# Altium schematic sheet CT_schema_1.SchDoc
size 729 x 589 mm
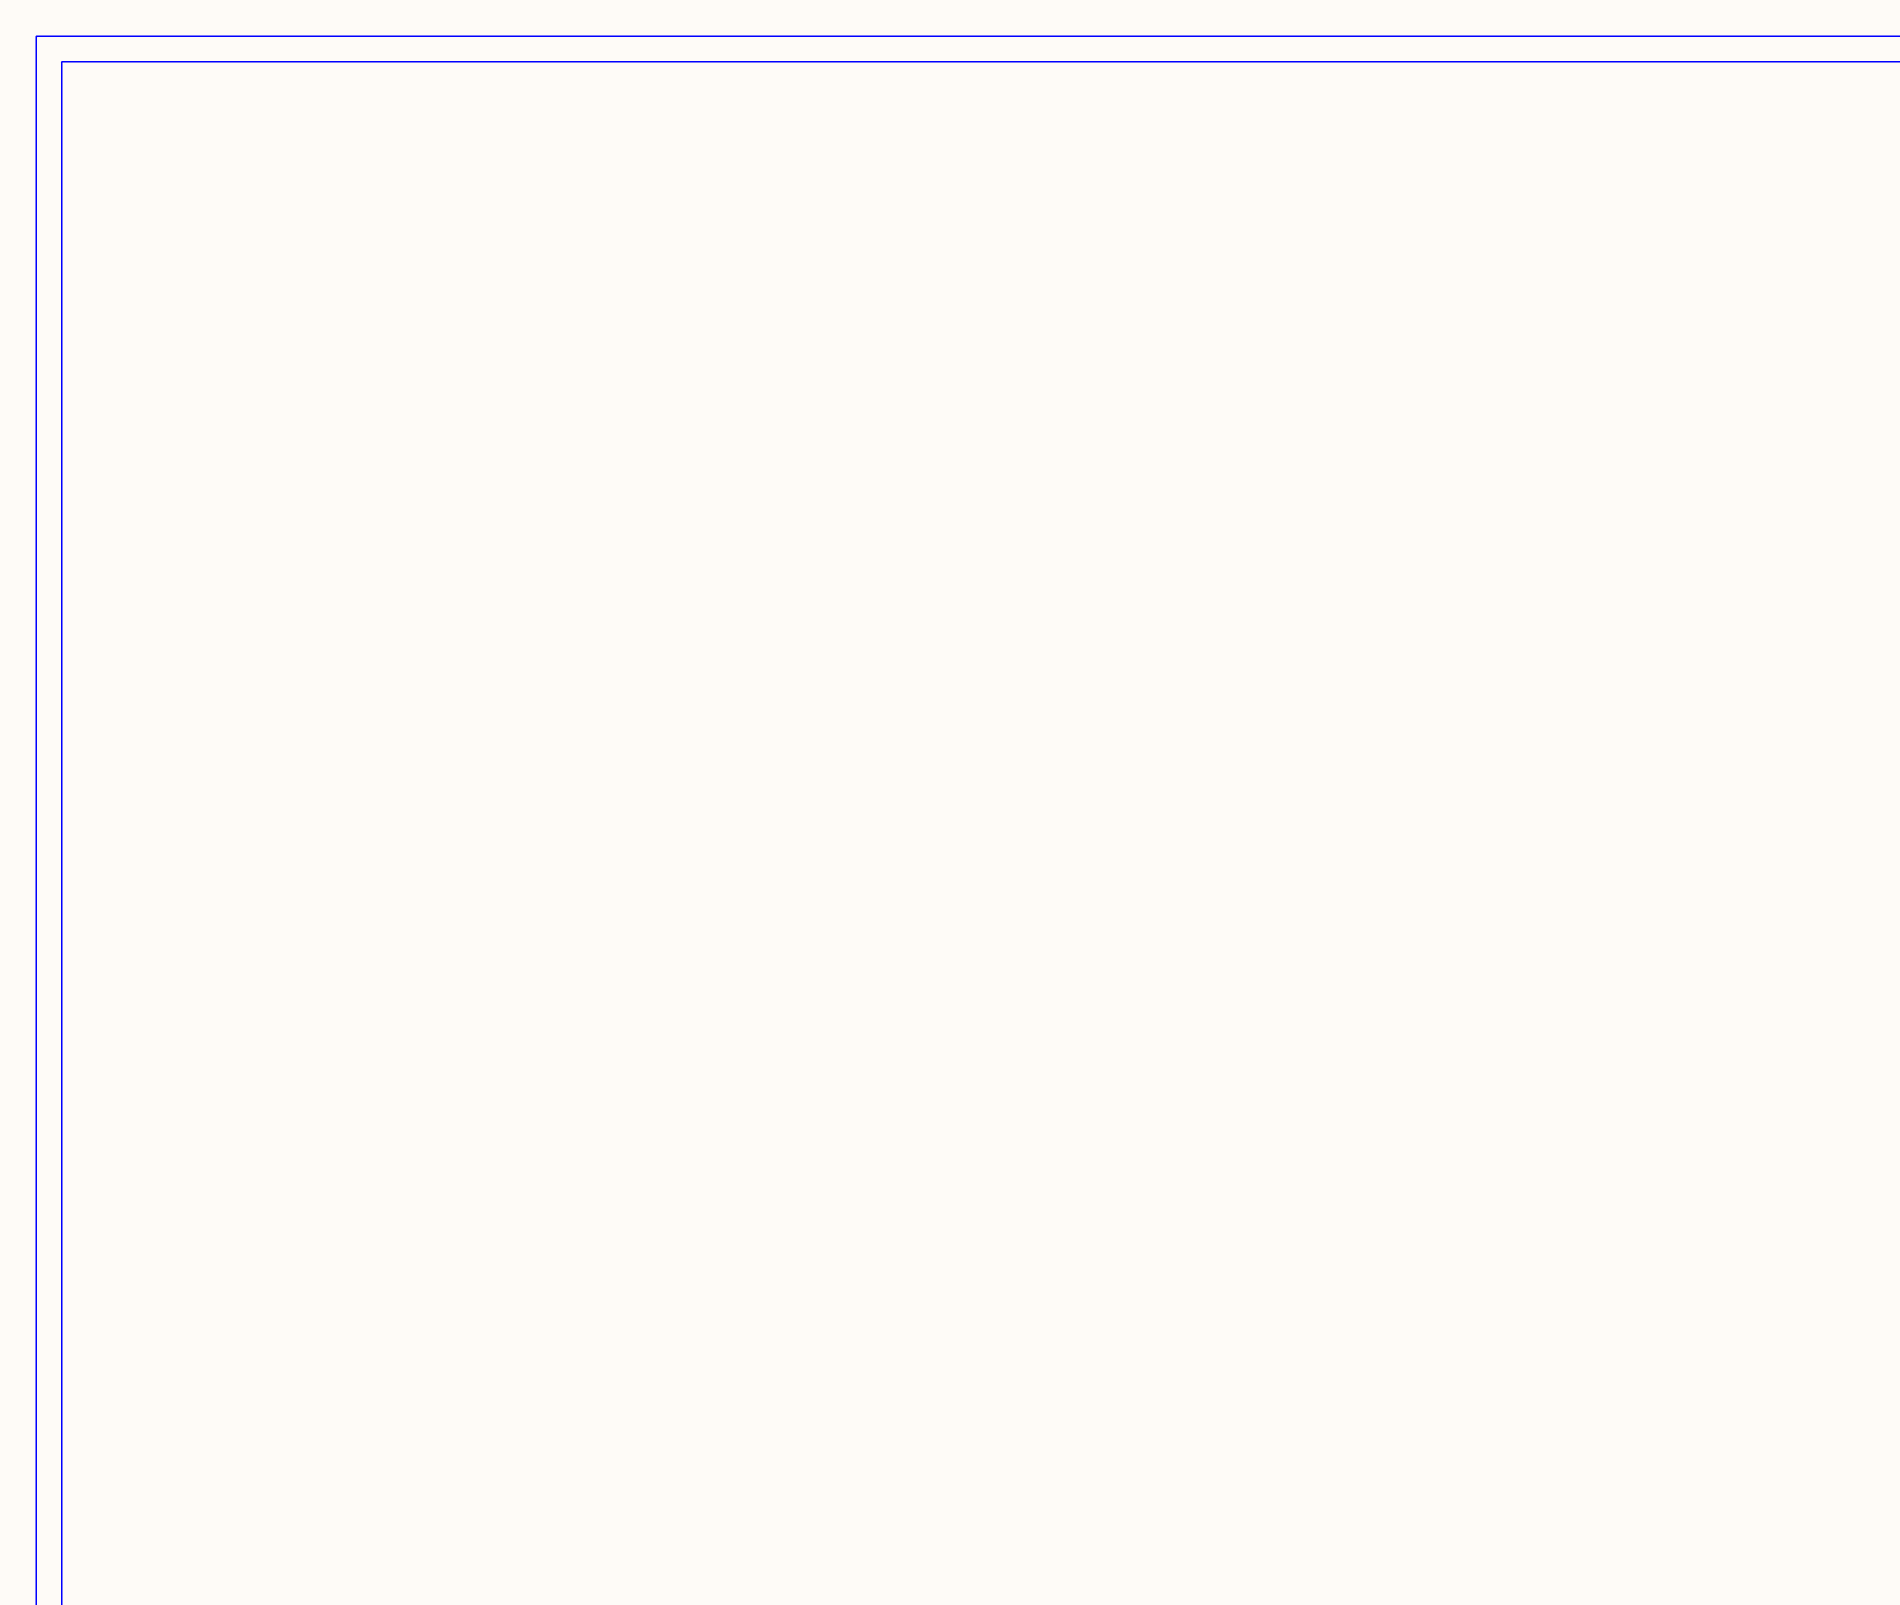
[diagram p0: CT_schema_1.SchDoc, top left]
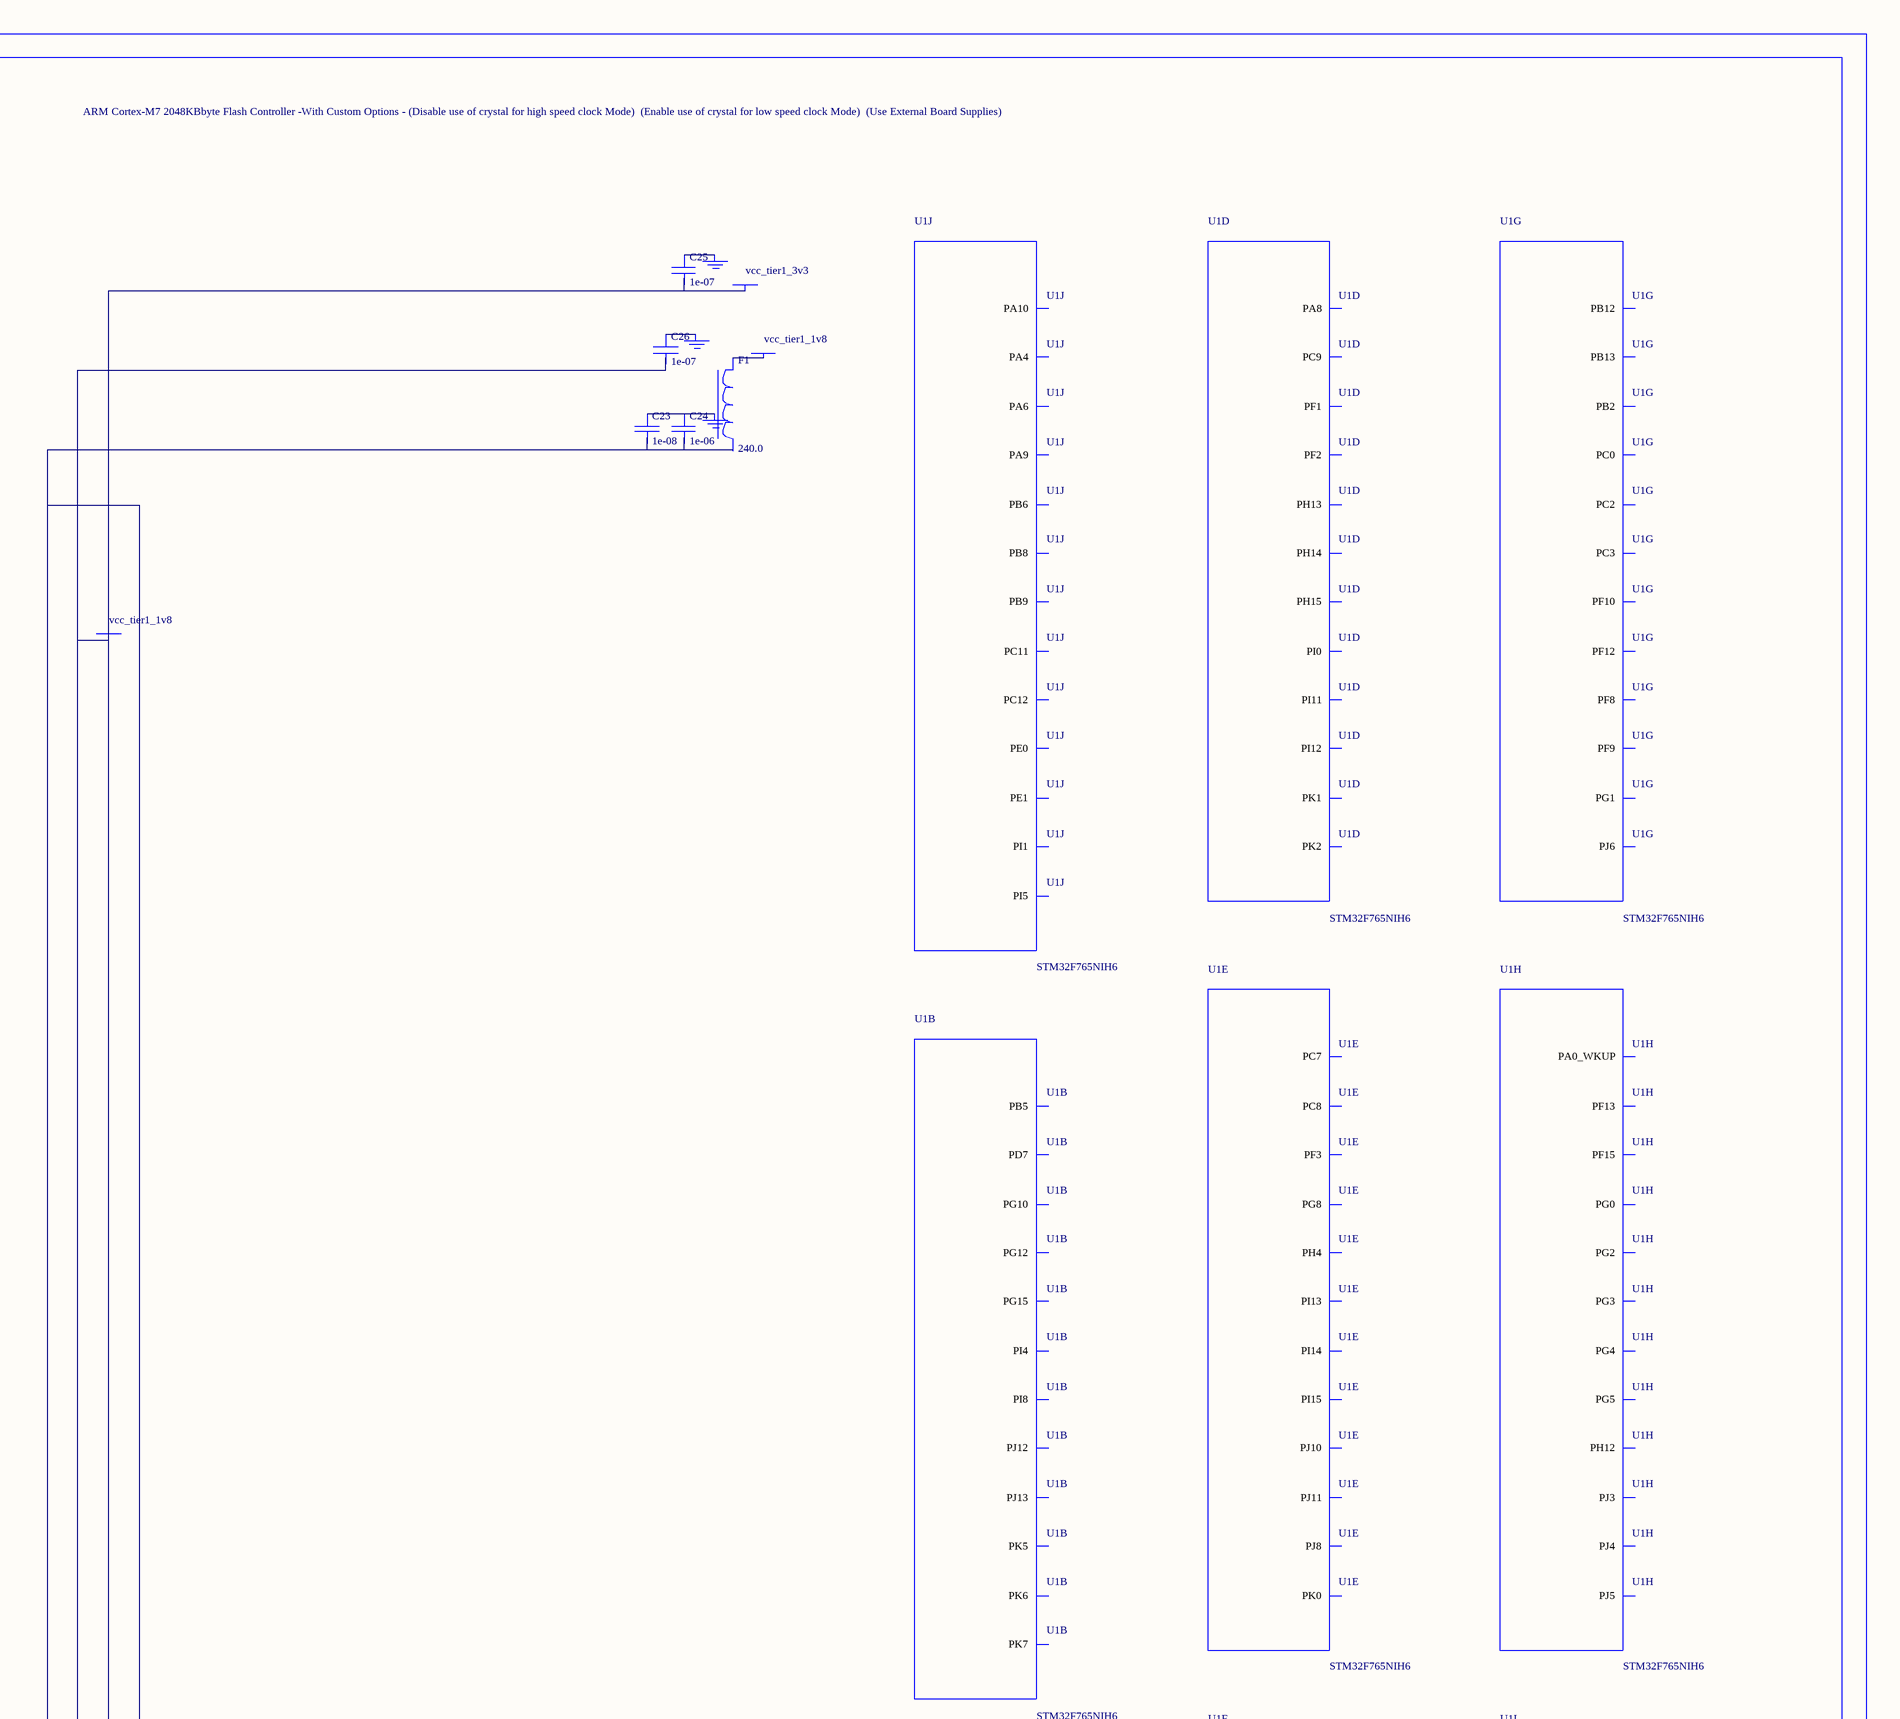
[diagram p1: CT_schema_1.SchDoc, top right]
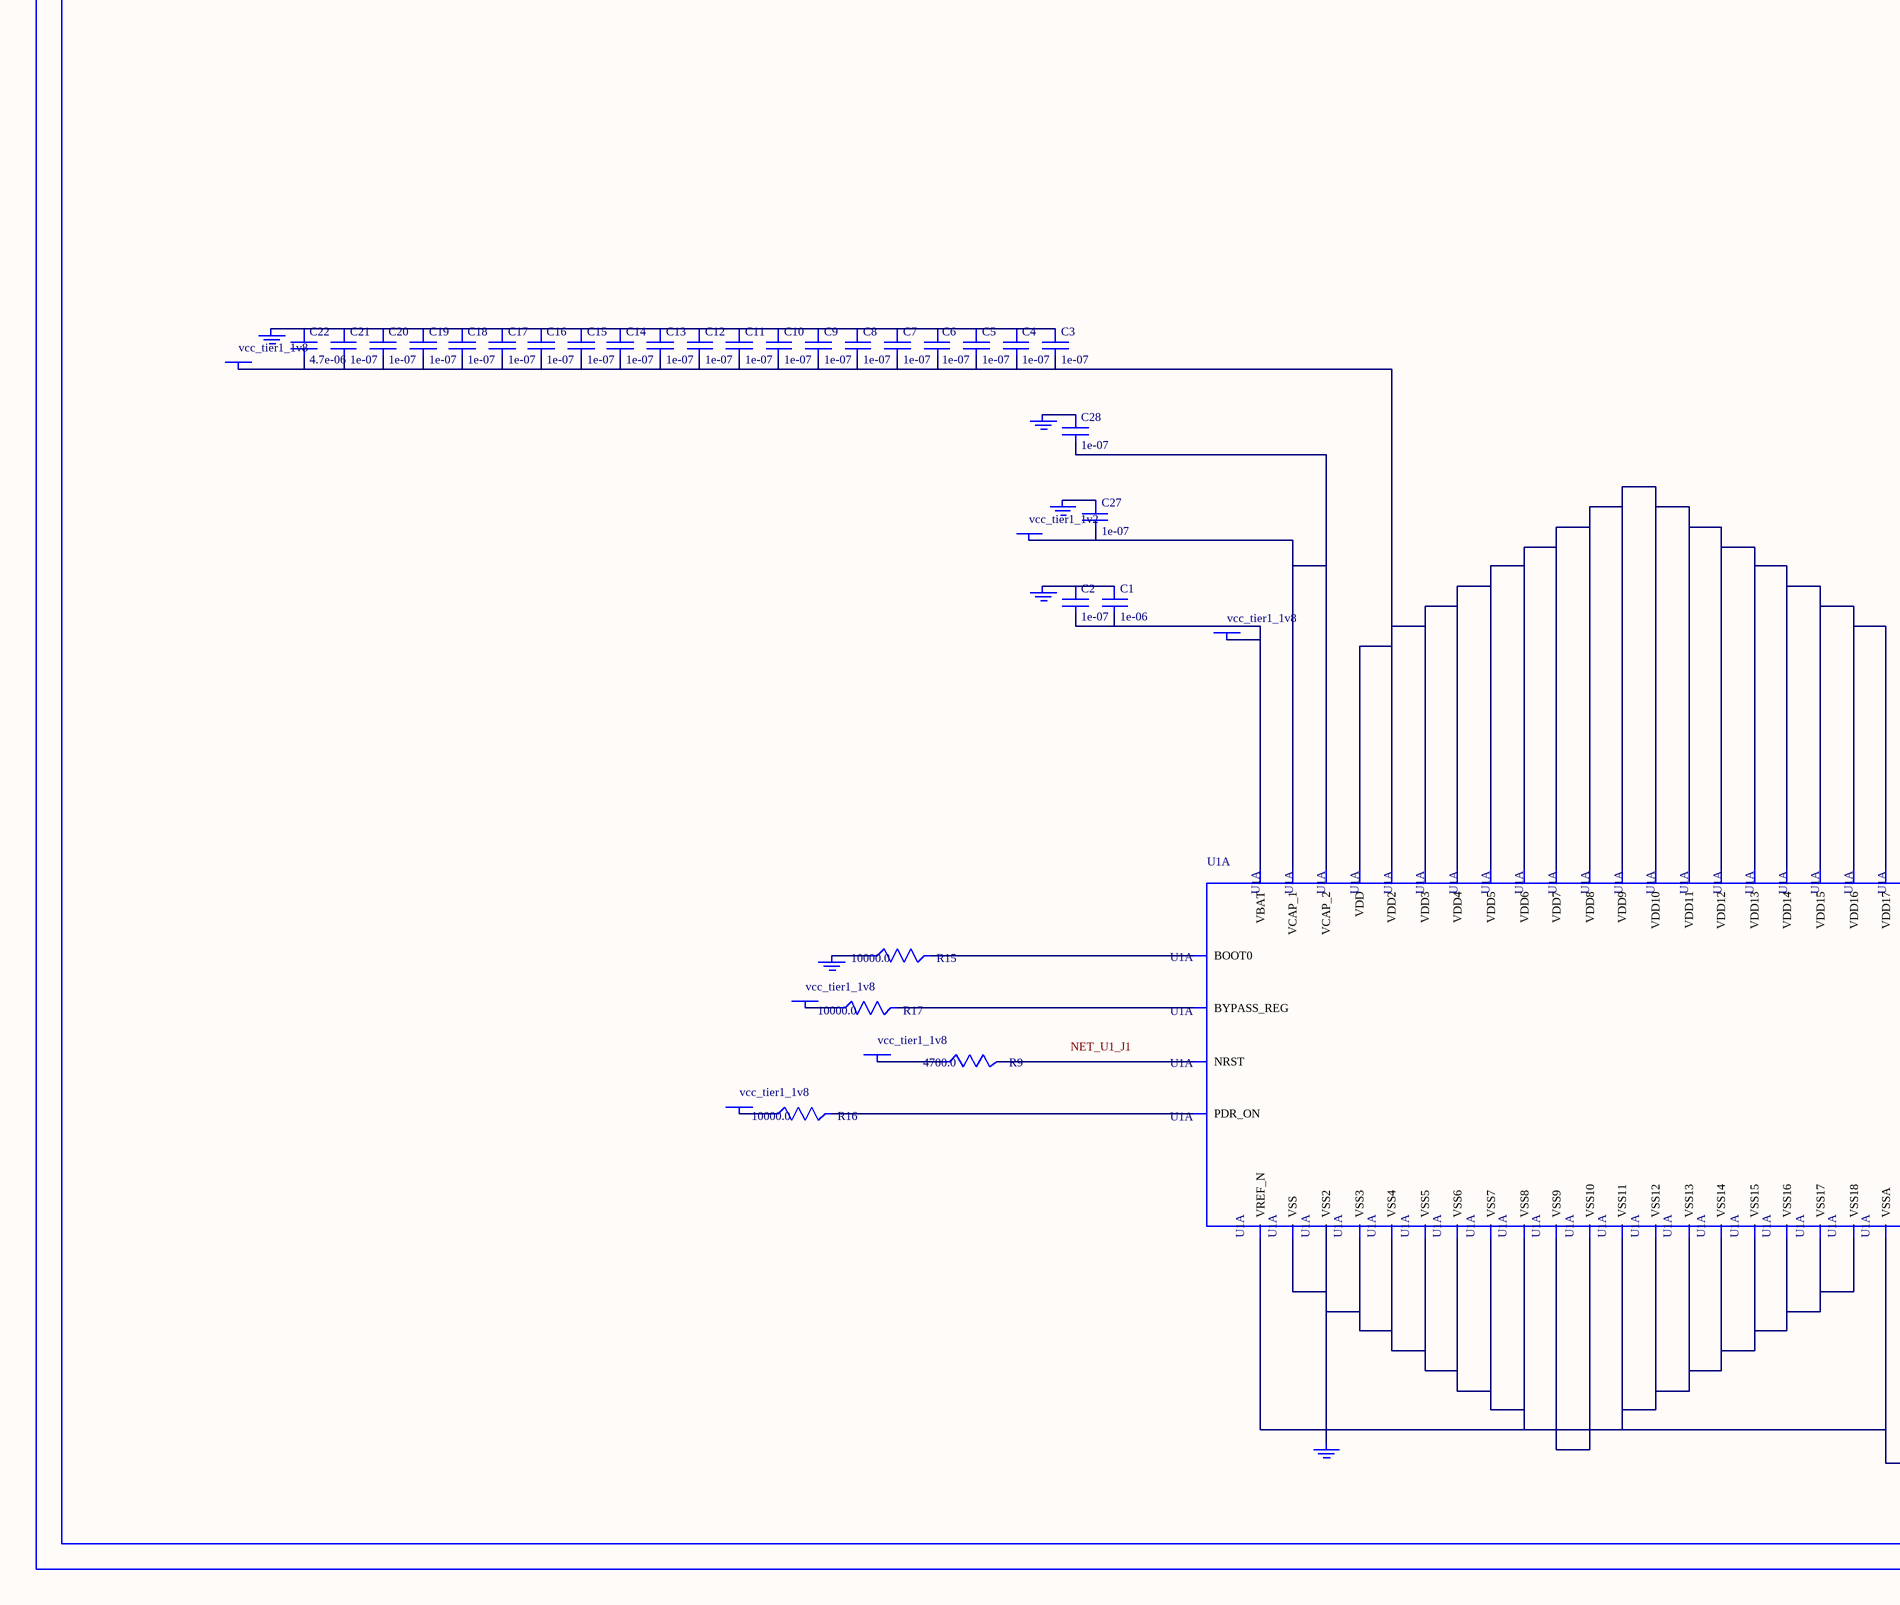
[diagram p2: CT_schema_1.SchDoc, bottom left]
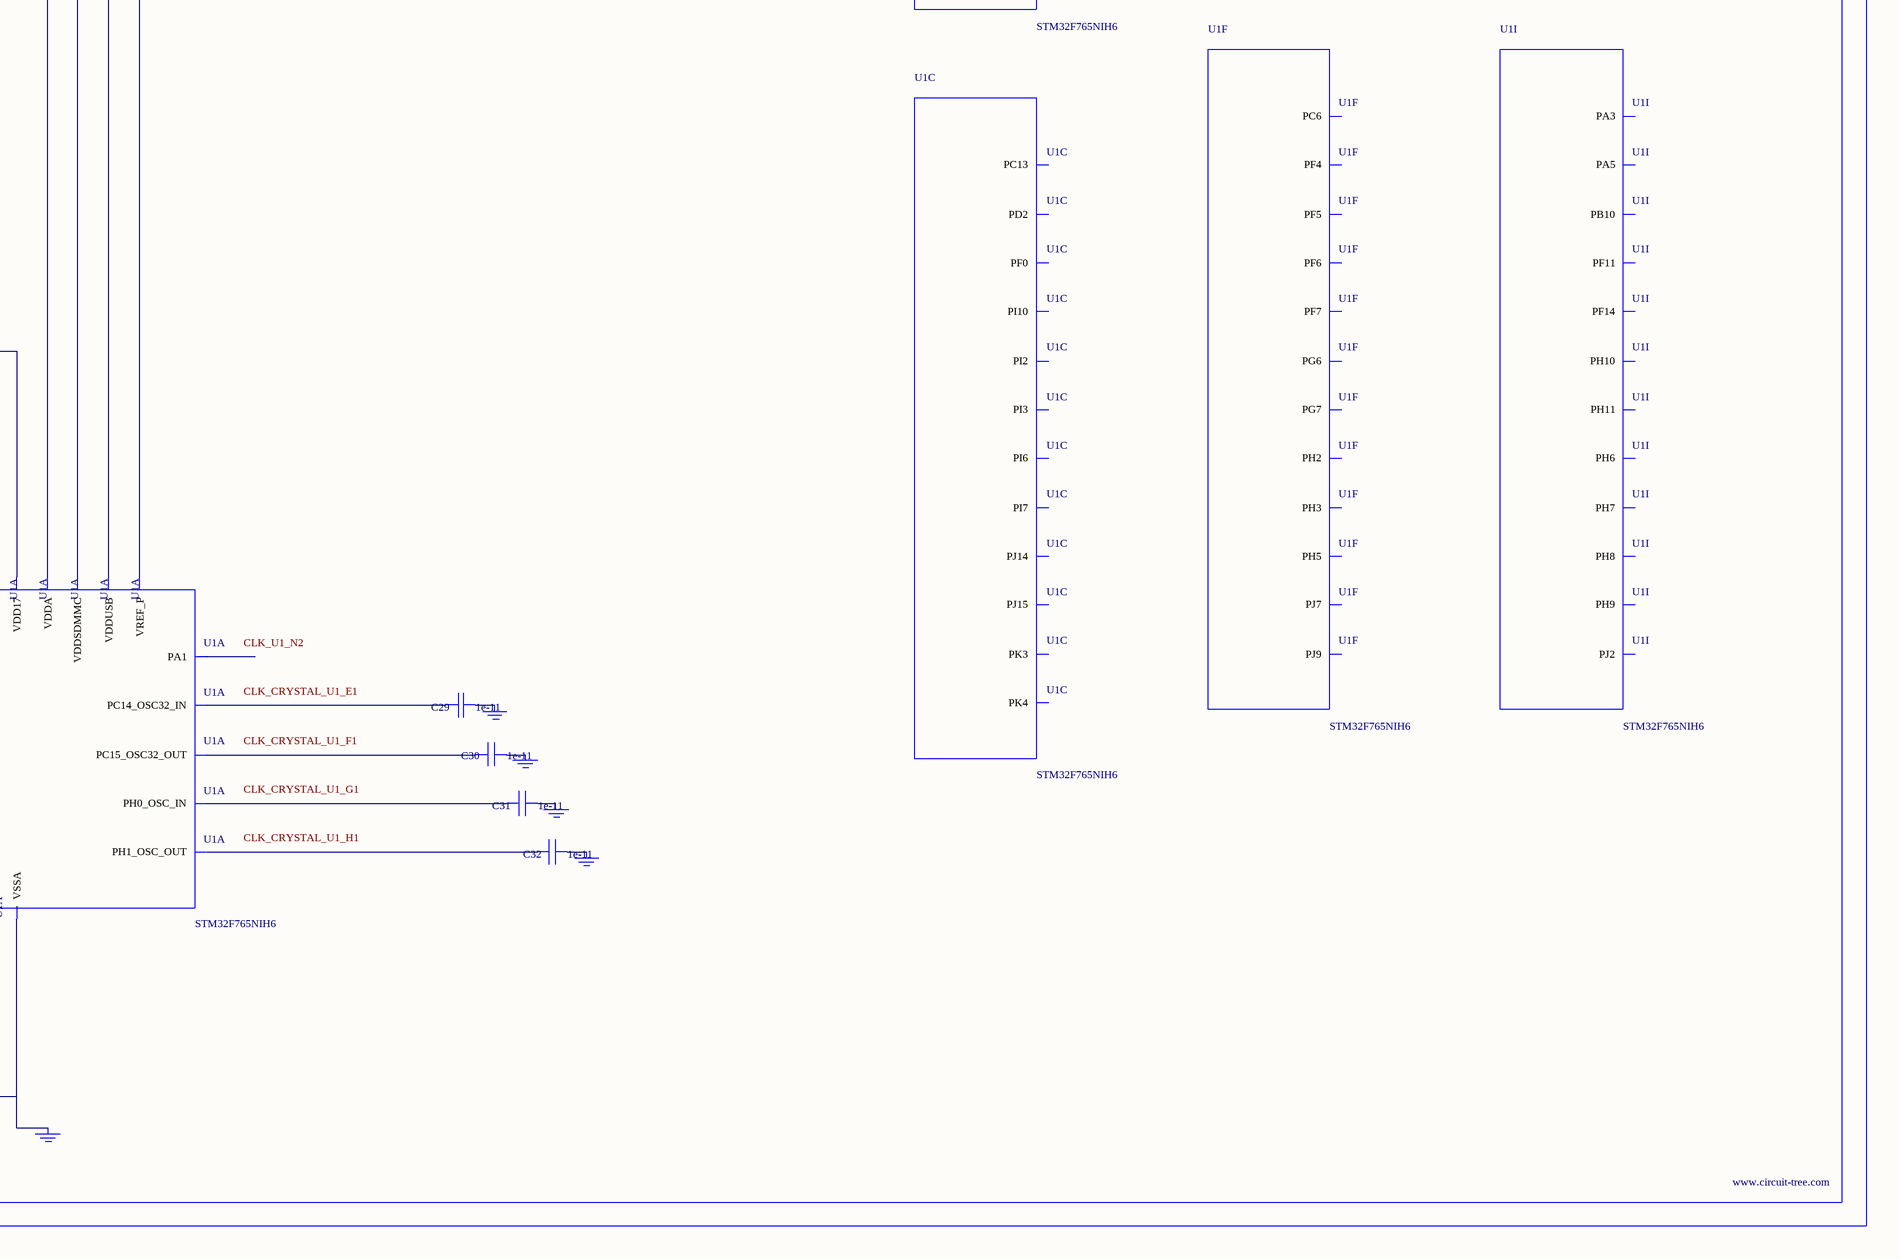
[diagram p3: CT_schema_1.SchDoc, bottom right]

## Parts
BORDER0  (no value)
C1  1e-06  [C0603]
C2  1e-07  [C0603]
C3  1e-07  [C0603]
C4  1e-07  [C0603]
C5  1e-07  [C0603]
C6  1e-07  [C0603]
C7  1e-07  [C0603]
C8  1e-07  [C0603]
C9  1e-07  [C0603]
C10  1e-07  [C0603]
C11  1e-07  [C0603]
C12  1e-07  [C0603]
C13  1e-07  [C0603]
C14  1e-07  [C0603]
C15  1e-07  [C0603]
C16  1e-07  [C0603]
C17  1e-07  [C0603]
C18  1e-07  [C0603]
C19  1e-07  [C0603]
C20  1e-07  [C0603]
C21  1e-07  [C0603]
C22  4.7e-06  [C0603]
C23  1e-08  [C0603]
C24  1e-06  [C0603]
C25  1e-07  [C0603]
C26  1e-07  [C0603]
C27  1e-07  [C0603]
C28  1e-07  [C0603]
C29  1e-11  [C0402]
C30  1e-11  [C0402]
C31  1e-11  [C0402]
C32  1e-11  [C0402]
F1  240.0  [L0603]
GND_INSTANCE_0_0  (no value)
GND_INSTANCE_0_1  (no value)
GND_INSTANCE_0_2  (no value)
GND_INSTANCE_0_3  (no value)
GND_INSTANCE_0_4  (no value)
GND_INSTANCE_0_5  (no value)
GND_INSTANCE_0_6  (no value)
GND_INSTANCE_0_7  (no value)
GND_INSTANCE_0_8  (no value)
GND_INSTANCE_0_9  (no value)
GND_INSTANCE_0_10  (no value)
GND_INSTANCE_0_11  (no value)
GND_INSTANCE_0_12  (no value)
GND_INSTANCE_0_13  (no value)
POWER_INSTANCE_0_0  vcc_tier1_1v8
POWER_INSTANCE_0_1  vcc_tier1_1v8
POWER_INSTANCE_0_2  vcc_tier1_1v8
POWER_INSTANCE_0_3  vcc_tier1_1v8
POWER_INSTANCE_0_4  vcc_tier1_3v3
POWER_INSTANCE_0_5  vcc_tier1_1v8
POWER_INSTANCE_0_6  vcc_tier1_1v8
POWER_INSTANCE_0_7  vcc_tier1_1v2
POWER_INSTANCE_0_8  vcc_tier1_1v8
R9  4700.0  [R0603]
R15  10000.0  [R0603]
R16  10000.0  [R0603]
R17  10000.0  [R0603]
U1  STM32F765NIH6  [TFBGA216]  (parts A,B,C,D,E,F,G,H,I,J of 15)

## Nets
NetC1_1: C1.1 C2.1 GND_INSTANCE_0_0.0(GND)
NetC1_2: C1.2 C2.2 POWER_INSTANCE_0_0.0(PWR) U1.C1(VBAT)
NetC3_1: C3.1 C4.1 C5.1 C6.1 C7.1 C8.1 C9.1 C10.1 C11.1 C12.1 C13.1 C14.1 C15.1 C16.1 C17.1 C18.1 C19.1 C20.1 C21.1 C22.1 GND_INSTANCE_0_2.0(GND)
NetC3_2: C3.2 C4.2 C5.2 C6.2 C7.2 C8.2 C9.2 C10.2 C11.2 C12.2 C13.2 C14.2 C15.2 C16.2 C17.2 C18.2 C19.2 C20.2 C21.2 C22.2 POWER_INSTANCE_0_2.0(PWR) U1.E7(VDD2) U1.E8(VDD3) U1.E10(VDD) U1.F4(VDD5) U1.F5(VDD6) U1.F11(VDD4) U1.G5(VDD7) U1.H5(VDD9) U1.H11(VDD8) U1.J5(VDD11) U1.J11(VDD10) U1.K5(VDD13) U1.K11(VDD12) U1.L7(VDD15) U1.L8(VDD16) U1.L9(VDD17) U1.L10(VDD14)
NetC23_1: C23.1 C24.1 GND_INSTANCE_0_1.0(GND)
NetC23_2: C23.2 C24.2 U1.P1(VREF_P) U1.R1(VDDA)
NetC25_1: C25.1 GND_INSTANCE_0_4.0(GND)
NetC25_2: C25.2 C26.2 POWER_INSTANCE_0_4.0(PWR) POWER_INSTANCE_0_5.0(PWR) U1.E9(VDDSDMMC) U1.G11(VDDUSB)
NetC26_1: C26.1 GND_INSTANCE_0_5.0(GND)
NetC27_1: C27.1 GND_INSTANCE_0_6.0(GND)
NetC27_2: C27.2 C28.2 POWER_INSTANCE_0_7.0(PWR) U1.E11(VCAP_2) U1.L11(VCAP_1)
NetC28_1: C28.1 GND_INSTANCE_0_7.0(GND)
NetC29_1: C29.1 GND_INSTANCE_0_8.0(GND)
NetC29_2: C29.2 U1.E1(PC14_OSC32_IN)
NetC30_1: C30.1 GND_INSTANCE_0_9.0(GND)
NetC30_2: C30.2 U1.F1(PC15_OSC32_OUT)
NetC31_1: C31.1 GND_INSTANCE_0_10.0(GND)
NetC31_2: C31.2 U1.G1(PH0_OSC_IN)
NetC32_1: C32.1 GND_INSTANCE_0_11.0(GND)
NetC32_2: C32.2 U1.H1(PH1_OSC_OUT)
NetF1_1: F1.1 POWER_INSTANCE_0_1.0(PWR)
NetGND_INSTANCE_0_3_0: GND_INSTANCE_0_3.0(GND) R15.1
NetGND_INSTANCE_0_12_0: GND_INSTANCE_0_12.0(GND) GND_INSTANCE_0_13.0(GND) U1.F2(VSS2) U1.F6(VSS3) U1.F7(VSS4) U1.F8(VSS5) U1.F9(VSS6) U1.F10(VSS) U1.G6(VSS8) U1.G10(VSS7) U1.H6(VSS10) U1.H10(VSS9) U1.J6(VSS12) U1.J10(VSS11) U1.K6(VSS14) U1.K7(VSS15) U1.K8(VSS16) U1.K9(VSS17) U1.K10(VSS13) U1.L6(VSS18) U1.M1(VSSA) U1.N1(VREF_N)
NetPOWER_INSTANCE_0_3_0: POWER_INSTANCE_0_3.0(PWR) R16.1
NetPOWER_INSTANCE_0_6_0: POWER_INSTANCE_0_6.0(PWR) R17.1
NetPOWER_INSTANCE_0_8_0: POWER_INSTANCE_0_8.0(PWR) R9.1
NetR9_2: R9.2 U1.J1(NRST)
NetR15_2: R15.2 U1.E6(BOOT0)
NetR16_2: R16.2 U1.E5(PDR_ON)
NetR17_2: R17.2 U1.L5(BYPASS_REG)

Not connected (* = marked no-connect by the designer): F1 2; U1 A5(PE1) A6(PE0) A7(PB8) A8(PB5) A11(PD7) A12(PC12) B4(PB9) B6(PB6) B7(PG15) B9(PJ13) B10(PJ12) B13(PC11) C2(PI8) C3(PI4) C4(PK7) C5(PK6) C6(PK5) C7(PG12) C8(PG10) C9(PJ14) C13(PI3) C14(PI2) D1(PC13) D2(PF0) D3(PI5) D4(PI7) D5(PI10) D6(PI6) D7(PK4) D8(PK3) D10(PJ15) D12(PD2) D13(PH15) D14(PI1) D15(PA10) E2(PF1) E3(PI12) E12(PH13) E13(PH14) E14(PI0) E15(PA9) F3(PI11) F12(PK1) F13(PK2) F14(PC9) F15(PA8) G2(PF2) G3(PI13) G4(PI15) G12(PJ11) G13(PK0) G14(PC8) G15(PC7) H2(PF3) H3(PI14) H4(PH4) H12(PJ8) H13(PJ10) H14(PG8) H15(PC6) J2(PF4) J3(PH5) J4(PH3) J12(PJ7) J13(PJ9) J14(PG7) J15(PG6) K1(PF7) K2(PF6) K3(PF5) K4(PH2) K12(PJ6) K14(PB13) L1(PF10) L2(PF9) L3(PF8) L4(PC3) L13(PB12) M2(PC0) M4(PC2) M5(PB2) M6(PF12) M7(PG1) M8(PF15) M9(PJ4) M12(PG3) M13(PG2) M14(PJ5) M15(PH12) N2(PA1) N3(PA0_WKUP) N4(PA4) N6(PF13) N7(PG0) N8(PJ3) N11(PG5) N12(PG4) N13(PH7) N14(PH9) N15(PH11) P3(PA6) P4(PA5) P6(PF14) P7(PJ2) P8(PF11) P12(PB10) P13(PH6) P14(PH8) P15(PH10) R2(PA3)

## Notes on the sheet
- Labels drawn without touching a wire or pin: CLK_CRYSTAL_U1_E1, CLK_CRYSTAL_U1_F1, CLK_CRYSTAL_U1_G1, CLK_CRYSTAL_U1_H1, CLK_U1_N2, NET_U1_J1

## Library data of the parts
BORDER0 = BORDER_PAGE0
C1 C24 = C0603C105K3RACTU
C2-C21 C25-C28 = 06035C104K4Z2A
C22 = GRM188R6YA475KE15D
C23 = 06035C103K4Z2A
C29-C32 = C0402C100K3GACTU
F1 = Z0603C241ASMST
GND_INSTANCE_0_0-GND_INSTANCE_0_13 = GND
POWER_INSTANCE_0_0-POWER_INSTANCE_0_8 = PWR
R9 = RC0603JR-074K7L
R15-R17 = RC0603JR-0710KL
